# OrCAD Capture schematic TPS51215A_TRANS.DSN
size E; title: TPS51215A Single Phase, D-CAP2TM Controller with 2-Bit; rev: 1.0; note: Datasheet: SLUSDW9A       EVM: SLUUC79
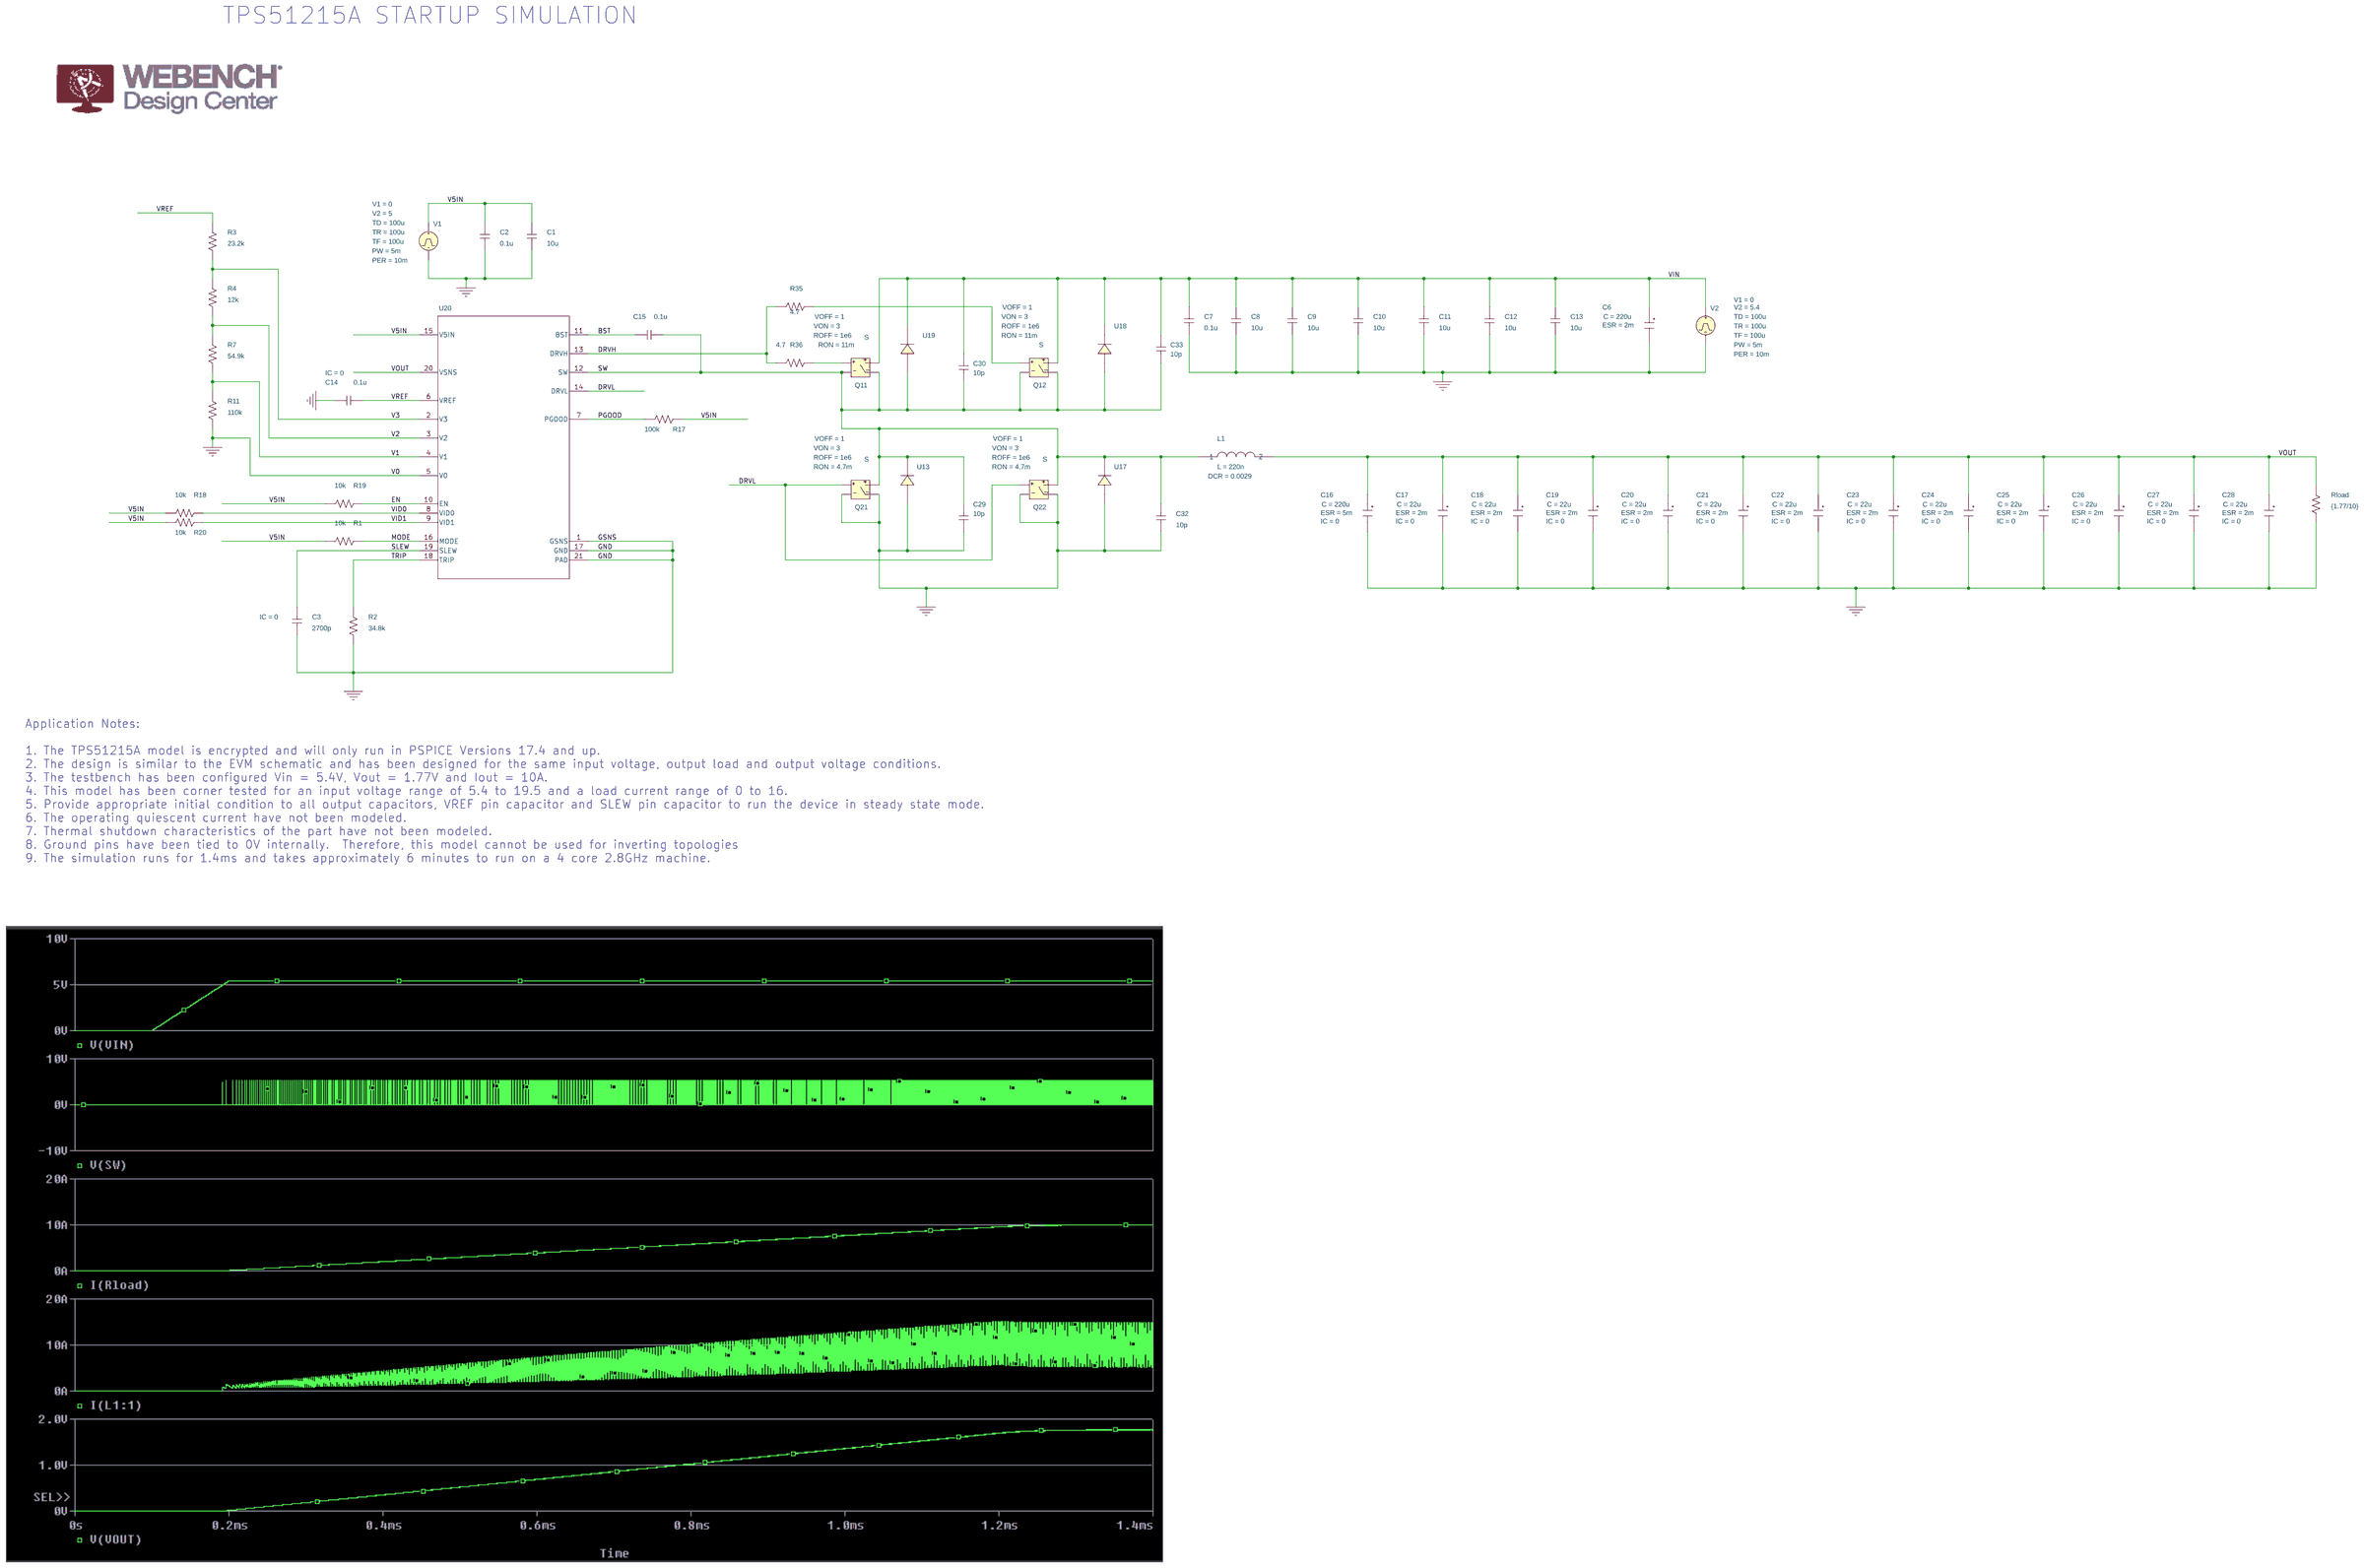
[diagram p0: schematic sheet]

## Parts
C1  10u  [cap196]
C2  0.1u  [cap196]
C3  2700p  [cap196]
C6  CESR
C7  0.1u  [RAD/CK05]
C8  10u  [RAD/CK05]
C9  10u  [RAD/CK05]
C10  10u  [RAD/CK05]
C11  10u  [RAD/CK05]
C12  10u  [RAD/CK05]
C13  10u  [RAD/CK05]
C14  0.1u  [cap196]
C15  0.1u  [RAD/CK05]
C16  CESR
C17  CESR
C18  CESR
C19  CESR
C20  CESR
C21  CESR
C22  CESR
C23  CESR
C24  CESR
C25  CESR
C26  CESR
C27  CESR
C28  CESR
C29  10p  [RAD/CK05]
C30  10p  [RAD/CK05]
C32  10p  [RAD/CK05]
C33  10p  [RAD/CK05]
L1  LDCR
Q11  S
Q12  S
Q21  S
Q22  S
R1  10k  [AXRC05]
R2  34.8k  [AXRC05]
R3  23.2k  [AXRC05]
R4  12k  [AXRC05]
R7  54.9k  [AXRC05]
R11  110k  [AXRC05]
R17  100k  [AXRC05]
R18  10k  [AXRC05]
R19  10k  [AXRC05]
R20  10k  [AXRC05]
R35  4.7  [AX/RC05]
R36  4.7  [AX/RC05]
Rload  {1.77/10}  [AX/RC05]
U13  D_D1
U17  D_D1
U18  D_D1
U19  D_D1
U20  TPS51215ARUK_TRANS  [RUK0020B]
V1  VPULSE
V2  VPULSE

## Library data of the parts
C1 C2 C7-C13 C15 C29 C30 C32 C33 = C
C3 C14 = C: IC: 0
C6 = CESR_0: C: 220u; ESR: 2m; PSpiceTemplate: X^@REFDES %IN %OUT @MODEL PARAMS:  ?C|C=@C||C=100u|  ?ESR|ESR=@ESR||ESR=0.01| ?X|X=@X||X=2|  ?IC|IC=@IC||IC=2|; X: 1
C16 = CESR_0: C: 220u; ESR: 5m; IC: 0; PSpiceTemplate: X^@REFDES %IN %OUT @MODEL PARAMS:  ?C|C=@C||C=100u|  ?ESR|ESR=@ESR||ESR=0.01| ?X|X=@X||X=2|  ?IC|IC=@IC||IC=2|; X: 1
C17-C28 = CESR_0: C: 22u; ESR: 2m; IC: 0; PSpiceTemplate: X^@REFDES %IN %OUT @MODEL PARAMS:  ?C|C=@C||C=100u|  ?ESR|ESR=@ESR||ESR=0.01| ?X|X=@X||X=2|  ?IC|IC=@IC||IC=2|; X: 1
L1 = LDCR: DCR: 0.0029; L: 220n
Q11 Q12 = S: ROFF: 1e6; RON: 11m; VOFF: 1; VON: 3
Q21 Q22 = S: ROFF: 1e6; RON: 4.7m; VOFF: 1; VON: 3
R1-R4 R7 R11 R17-R20 R35 R36 Rload = R
U13 U17-U19 = D_D1
U20 = TPS51215ARUK_TRANS
V1 = VPULSE: PER: 10m; PW: 5m; TD: 100u; TF: 100u; TR: 100u; V1: 0; V2: 5
V2 = VPULSE: PER: 10m; PW: 5m; TD: 100u; TF: 100u; TR: 100u; V1: 0; V2: 5.4

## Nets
V1: R7.2 R11.1 U20.4(V1)
V2: R4.2 R7.1 U20.3(V2)
V3: R3.2 R4.1 U20.2(V3)
V5IN: C1.1 C2.1 R1.1 R17.2 R18.1 R19.1 R20.1 U20.15(V5IN) V1.1(+)
VIN: C6.1(IN) C7.1 C8.1 C9.1 C10.1 C11.1 C12.1 C13.1 C30.2 C33.2 Q11.2(3) Q12.2(3) U18.2 U19.2 V2.1(+)
0: C1.2 C2.2 C3.2 C6.2(OUT) C7.2 C8.2 C9.2 C10.2 C11.2 C12.2 C13.2 C14.2 C16.2(OUT) C17.2(OUT) C18.2(OUT) C19.2(OUT) C20.2(OUT) C21.2(OUT) C22.2(OUT) C23.2(OUT) C24.2(OUT) C25.2(OUT) C26.2(OUT) C27.2(OUT) C28.2(OUT) C29.1 C32.1 Q21.1(2) Q21.3(4) Q22.1(2) Q22.3(4) R2.2 R11.2 Rload.2 U13.1 U17.1 U20.1(GSNS) U20.5(V0) U20.17(GND) U20.21(PAD) V1.2(-) V2.2(-)
BST: C15.2 U20.11(BST)
DRVH: R35.1 R36.1 U20.13(DRVH)
DRVL: Q21.0(1) Q22.0(1) U20.14(DRVL)
EN: R19.2 U20.10(EN)
MODE: R1.2 U20.16(MODE)
PGOOD: R17.1 U20.7(PGOOD)
SLEW: C3.1 U20.19(SLEW)
SW: C15.1 C29.2 C30.1 C32.2 C33.1 L1.1 Q11.1(2) Q11.3(4) Q12.1(2) Q12.3(4) Q21.2(3) Q22.2(3) U13.2 U17.2 U18.1 U19.1 U20.12(SW)
TRIP: R2.1 U20.18(TRIP)
VID0: R18.2 U20.8(VID0)
VID1: R20.2 U20.9(VID1)
VOUT: C16.1(IN) C17.1(IN) C18.1(IN) C19.1(IN) C20.1(IN) C21.1(IN) C22.1(IN) C23.1(IN) C24.1(IN) C25.1(IN) C26.1(IN) C27.1(IN) C28.1(IN) L1.2 Rload.1 U20.20(VSNS)
VREF: C14.1 R3.1 U20.6(VREF)
N16776932: Q12.0(1) R35.2
N16777315: Q11.0(1) R36.2

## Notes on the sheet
- TPS51215A STARTUP SIMULATION
- Application Notes:
  1. The TPS51215A model is encrypted and will only run in PSPICE Versions 17.4 and up.
  2. The design is similar to the EVM schematic and has been designed for the same input voltage, output load and output voltage conditions.
  3. The testbench has been configured Vin = 5.4V, Vout = 1.77V and Iout = 10A.
  4. This model has been corner tested for an input voltage range of 5.4 to 19.5 and a load current range of 0 to 16.
  5. Provide appropriate initial condition to all output capacitors, VREF pin capacitor and SLEW pin capacitor to run the device in steady state mode.
  6. The operating quiescent current have not been modeled.
  7. Thermal shutdown characteristics of the part have not been modeled.
  8. Ground pins have been tied to 0V internally.  Therefore, this model cannot be used for inverting topologies
  9. The simulation runs for 1.4ms and takes approximately 6 minutes to run on a 4 core 2.8GHz machine.
